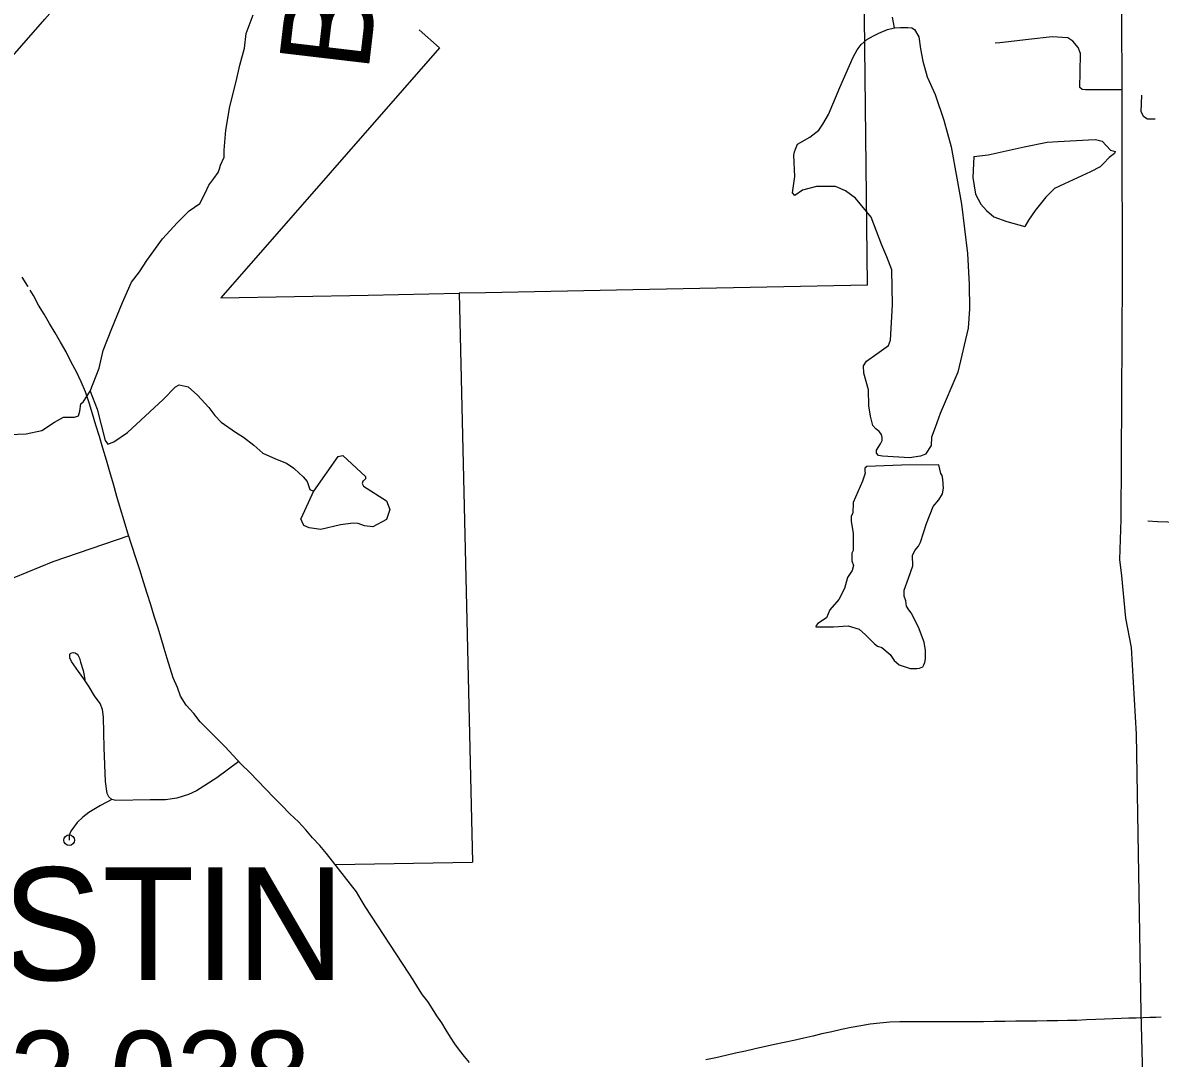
# Model space of a CAD drawing. Extents: x 1367863 to 1368197, y 380048 to 380261.
# Drawn here: x 1367991.45 to 1368012.13, y 380131.45 to 380150.28 of the extents above; entities that cross this region are included whole.
import ezdxf

# ---------------------------------------------------------------- set-up
doc = ezdxf.new("R2010")
doc.units = 0
for name, color, linetype in [('Level 10', 7, 'Continuous'), ('Level 33', 7, 'Continuous'), ('Level 35', 7, 'Continuous'), ('Level 40', 7, 'Continuous'), ('Level 6', 7, 'Continuous')]:
    doc.layers.add(name, color=color, linetype=linetype)

msp = doc.modelspace()

# ---------------------------------------------------------------- linework, layer by layer
at = {"layer": 'Level 10'}
msp.add_lwpolyline([(1368011.429, 380151.098), (1368011.439, 380145.66), (1368011.416, 380141.25), (1368011.392, 380140.52), (1368011.431, 380140.222), (1368011.504, 380139.453), (1368011.603, 380138.92), (1368011.693, 380137.345), (1368011.778, 380132.275), (1368011.845, 380129.756)], dxfattribs=at)
at = {"layer": 'Level 33'}
for points in [[(1368011.433, 380149.062), (1368010.774, 380149.061), (1368010.716, 380149.072), (1368010.669, 380149.107), (1368010.675, 380149.386), (1368010.681, 380149.724), (1368010.64, 380149.834), (1368010.547, 380149.951), (1368010.454, 380150.009), (1368010.169, 380150.026), (1368009.739, 380149.98), (1368009.216, 380149.916), (1368009.131, 380149.914)], [(1368012.041, 380148.531), (1368011.9, 380148.53), (1368011.836, 380148.571), (1368011.784, 380148.664), (1368011.796, 380148.966)], [(1367991.541, 380145.483), (1367991.537, 380145.49), (1367991.435, 380145.654)], [(1367997.518, 380134.473), (1367996.972, 380135.175), (1367996.846, 380135.316), (1367996.717, 380135.46), (1367996.591, 380135.604), (1367996.461, 380135.749), (1367996.305, 380135.896), (1367996.16, 380136.044), (1367996.014, 380136.193), (1367995.869, 380136.342), (1367995.721, 380136.494), (1367995.573, 380136.646), (1367995.417, 380136.8), (1367995.271, 380136.957), (1367995.124, 380137.112), (1367994.975, 380137.265), (1367994.825, 380137.418), (1367994.674, 380137.567), (1367994.559, 380137.72), (1367994.415, 380137.874), (1367994.317, 380138.032), (1367994.257, 380138.192), (1367994.178, 380138.368), (1367994.128, 380138.542), (1367994.074, 380138.72), (1367994.015, 380138.901), (1367993.961, 380139.092), (1367993.9, 380139.289), (1367993.837, 380139.49), (1367993.772, 380139.695), (1367993.706, 380139.903), (1367993.64, 380140.116), (1367993.573, 380140.332), (1367993.501, 380140.551), (1367993.428, 380140.773), (1367993.358, 380140.997), (1367993.292, 380141.225), (1367993.222, 380141.443), (1367993.157, 380141.665), (1367993.095, 380141.894), (1367993.03, 380142.114), (1367992.966, 380142.329), (1367992.904, 380142.544), (1367992.842, 380142.757), (1367992.777, 380142.967), (1367992.714, 380143.171), (1367992.651, 380143.369), (1367992.584, 380143.568), (1367992.508, 380143.755), (1367992.421, 380143.933), (1367992.325, 380144.111), (1367992.237, 380144.301), (1367992.134, 380144.476), (1367992.032, 380144.644), (1367991.932, 380144.813), (1367991.836, 380144.983), (1367991.732, 380145.146), (1367991.638, 380145.323), (1367991.578, 380145.421)], [(1368016.652, 380141.063), (1368016.403, 380141.048), (1368015.83, 380141.068), (1368015.058, 380141.093), (1368014.301, 380141.113), (1368013.479, 380141.148), (1368012.642, 380141.188), (1368012.084, 380141.207), (1368011.907, 380141.218)], [(1367993.372, 380140.951), (1367991.99, 380140.48), (1367991.286, 380140.188), (1367991.207, 380140.128), (1367991.129, 380140.017), (1367991.068, 380139.864), (1367991.05, 380139.641), (1367991.045, 380139.294)], [(1367995.375, 380136.846), (1367994.974, 380136.547), (1367994.605, 380136.312), (1367994.461, 380136.245), (1367994.25, 380136.177), (1367994.039, 380136.149), (1367993.765, 380136.149), (1367993.137, 380136.139), (1367993.065, 380136.158), (1367993.008, 380136.206), (1367992.979, 380136.264), (1367992.95, 380136.48), (1367992.926, 380137.094), (1367992.912, 380137.655), (1367992.893, 380137.794), (1367992.854, 380137.9), (1367992.749, 380138.039), (1367992.653, 380138.207), (1367992.557, 380138.35), (1367992.461, 380138.485), (1367992.332, 380138.667), (1367992.303, 380138.734), (1367992.303, 380138.797), (1367992.317, 380138.816), (1367992.361, 380138.83), (1367992.399, 380138.825), (1367992.432, 380138.801), (1367992.456, 380138.773), (1367992.476, 380138.729), (1367992.495, 380138.653), (1367992.543, 380138.504), (1367992.562, 380138.408), (1367992.576, 380138.331)], [(1367993.065, 380136.158), (1367992.859, 380136.045), (1367992.648, 380135.92), (1367992.538, 380135.834), (1367992.437, 380135.738), (1367992.317, 380135.58), (1367992.289, 380135.508), (1367992.289, 380135.416)], [(1367999.571, 380131.374), (1367999.479, 380131.481), (1367999.388, 380131.595), (1367999.303, 380131.712), (1367999.224, 380131.835), (1367999.147, 380131.962), (1367999.067, 380132.091), (1367998.975, 380132.218), (1367998.899, 380132.349), (1367998.815, 380132.48), (1367998.718, 380132.605), (1367998.633, 380132.734), (1367998.545, 380132.874), (1367998.468, 380132.998), (1367997.676, 380134.211), (1367997.599, 380134.331), (1367997.518, 380134.473)], [(1368012.151, 380132.196), (1368012.051, 380132.192), (1368011.942, 380132.191), (1368011.823, 380132.186), (1368011.696, 380132.18), (1368011.562, 380132.175), (1368011.421, 380132.169), (1368011.273, 380132.164), (1368011.119, 380132.157), (1368010.96, 380132.151), (1368010.794, 380132.145), (1368010.619, 380132.137), (1368010.445, 380132.136), (1368010.265, 380132.131), (1368010.079, 380132.128), (1368009.89, 380132.126), (1368009.699, 380132.124), (1368009.506, 380132.123), (1368009.312, 380132.12), (1368009.115, 380132.115), (1368008.919, 380132.112), (1368008.722, 380132.11), (1368008.527, 380132.111), (1368008.335, 380132.111), (1368008.146, 380132.114), (1368007.955, 380132.112), (1368007.765, 380132.112), (1368007.577, 380132.111), (1368007.395, 380132.109), (1368007.214, 380132.103), (1368007.035, 380132.089), (1368006.86, 380132.069), (1368006.686, 380132.041), (1368006.51, 380132.007), (1368006.334, 380131.97), (1368006.158, 380131.932), (1368005.981, 380131.892), (1368005.815, 380131.853), (1368005.65, 380131.813), (1368005.469, 380131.771), (1368005.294, 380131.734), (1368005.119, 380131.696), (1368004.765, 380131.618), (1368004.588, 380131.58), (1368004.409, 380131.539), (1368004.23, 380131.497), (1368004.05, 380131.455), (1368003.871, 380131.421)]]:
    msp.add_lwpolyline(points, dxfattribs=at)
msp.add_circle((1367992.289, 380135.416), 0.097, dxfattribs=at)
at = {"layer": 'Level 35'}
for points in [[(1367995.002, 380147.561), (1367995.023, 380147.628), (1367995.04, 380147.691), (1367995.107, 380147.842), (1367995.111, 380147.967), (1367995.136, 380148.332), (1367995.212, 380148.759), (1367995.329, 380149.216), (1367995.396, 380149.513), (1367995.48, 380149.819), (1367995.509, 380150.087), (1367995.635, 380150.426)], [(1368007.301, 380150.194), (1368007.264, 380150.387)], [(1368007.662, 380150.159), (1368007.743, 380150.026), (1368007.772, 380149.811), (1368007.813, 380149.584), (1368007.895, 380149.299), (1368008.04, 380148.979), (1368008.197, 380148.513), (1368008.331, 380148.025), (1368008.435, 380147.455), (1368008.517, 380146.983), (1368008.627, 380146.084), (1368008.656, 380145.52), (1368008.662, 380145.078), (1368008.639, 380144.728), (1368008.453, 380143.928), (1368008.133, 380143.178), (1368008.04, 380142.922), (1368007.976, 380142.747), (1368007.97, 380142.596), (1368007.866, 380142.439), (1368007.772, 380142.398), (1368007.575, 380142.369), (1368007.08, 380142.398), (1368007.011, 380142.41), (1368006.976, 380142.456), (1368006.976, 380142.509), (1368007.046, 380142.625), (1368007.075, 380142.683), (1368007.075, 380142.742), (1368007.063, 380142.794), (1368007.022, 380142.852), (1368006.964, 380142.899), (1368006.906, 380142.957), (1368006.865, 380143.126), (1368006.836, 380143.317), (1368006.825, 380143.608), (1368006.743, 380143.911), (1368006.737, 380144.045), (1368006.79, 380144.126), (1368006.982, 380144.26), (1368007.191, 380144.411), (1368007.226, 380144.51), (1368007.267, 380145.156), (1368007.249, 380145.79), (1368007.162, 380146.028), (1368007.069, 380146.238), (1368006.877, 380146.746), (1368006.592, 380147.095), (1368006.412, 380147.229), (1368006.226, 380147.304), (1368005.882, 380147.304), (1368005.627, 380147.24), (1368005.487, 380147.141), (1368005.446, 380147.188), (1368005.487, 380147.49), (1368005.47, 380147.874), (1368005.481, 380147.938), (1368005.499, 380147.985), (1368005.539, 380148.077)], [(1368005.539, 380148.077), (1368005.76, 380148.205), (1368005.923, 380148.333), (1368005.999, 380148.437), (1368006.098, 380148.618), (1368006.307, 380149.106), (1368006.551, 380149.659), (1368006.621, 380149.793), (1368006.697, 380149.886), (1368006.796, 380149.979), (1368006.918, 380150.049), (1368007.016, 380150.095), (1368007.174, 380150.159), (1368007.301, 380150.194), (1368007.412, 380150.2), (1368007.546, 380150.2), (1368007.615, 380150.194), (1368007.662, 380150.159)], [(1368008.744, 380147.85), (1368009.005, 380147.879), (1368009.657, 380148.025), (1368010.075, 380148.112), (1368010.279, 380148.124), (1368010.831, 380148.153), (1368010.954, 380148.159), (1368011.076, 380148.129), (1368011.227, 380147.967), (1368011.314, 380147.943), (1368011.302, 380147.908), (1368011.204, 380147.833), (1368011.099, 380147.722), (1368011.041, 380147.664), (1368010.866, 380147.571), (1368010.395, 380147.356), (1368010.209, 380147.268), (1368010.052, 380147.111), (1368009.86, 380146.867), (1368009.738, 380146.692), (1368009.668, 380146.576)], [(1368008.744, 380147.85), (1368008.726, 380147.471), (1368008.773, 380147.163), (1368008.872, 380146.983), (1368008.976, 380146.866), (1368009.11, 380146.756), (1368009.343, 380146.669), (1368009.668, 380146.576)], [(1367991.053, 380142.789), (1367991.509, 380142.806), (1367991.79, 380142.869), (1367992.025, 380143.019), (1367992.188, 380143.107), (1367992.385, 380143.112), (1367992.46, 380143.133), (1367992.481, 380143.221), (1367992.502, 380143.35), (1367992.548, 380143.397), (1367992.67, 380143.581), (1367992.833, 380144), (1367992.908, 380144.322), (1367993.063, 380144.72), (1367993.26, 380145.198), (1367993.423, 380145.567), (1367993.566, 380145.751), (1367993.704, 380145.96), (1367993.985, 380146.354), (1367994.257, 380146.652), (1367994.474, 380146.865), (1367994.667, 380146.999), (1367994.763, 380147.184), (1367994.83, 380147.33), (1367994.918, 380147.452), (1367995.002, 380147.561)], [(1367992.67, 380143.581), (1367992.796, 380143.257), (1367992.943, 380142.683), (1367992.995, 380142.62), (1367993.099, 380142.662), (1367993.35, 380142.829), (1367993.997, 380143.434), (1367994.226, 380143.664), (1367994.289, 380143.695), (1367994.456, 380143.664), (1367994.623, 380143.507), (1367994.832, 380143.288), (1367994.936, 380143.142), (1367995.051, 380143.017), (1367995.312, 380142.839), (1367995.458, 380142.745), (1367995.646, 380142.599), (1367995.813, 380142.453), (1367996.042, 380142.349), (1367996.241, 380142.275), (1367996.376, 380142.181), (1367996.387, 380142.171), (1367996.543, 380142.025), (1367996.617, 380141.941), (1367996.669, 380141.795), (1367996.732, 380141.764)], [(1367997.178, 380142.395), (1367997.267, 380142.414), (1367997.681, 380142.032), (1367997.681, 380141.987), (1367997.637, 380141.943), (1367997.63, 380141.943), (1367997.617, 380141.904), (1367997.643, 380141.853), (1367998.063, 380141.586), (1367998.121, 380141.433), (1367998.063, 380141.248), (1367997.815, 380141.114), (1367997.662, 380141.133), (1367997.547, 380141.178), (1367997.452, 380141.184), (1367997.222, 380141.152), (1367996.865, 380141.069), (1367996.655, 380141.095), (1367996.56, 380141.139), (1367996.528, 380141.203), (1367996.502, 380141.261)], [(1367997.178, 380142.395), (1367996.732, 380141.764), (1367996.502, 380141.261)], [(1368006.799, 380142.21), (1368006.761, 380142.181), (1368006.761, 380142.124), (1368006.767, 380142.089), (1368006.718, 380141.948), (1368006.551, 380141.555), (1368006.542, 380141.362), (1368006.511, 380141.307), (1368006.511, 380141.221), (1368006.548, 380140.993), (1368006.548, 380140.685), (1368006.525, 380140.633), (1368006.525, 380140.499), (1368006.557, 380140.412), (1368006.531, 380140.323), (1368006.447, 380140.193), (1368006.389, 380139.994), (1368006.291, 380139.795), (1368006.127, 380139.608), (1368006.061, 380139.458), (1368005.905, 380139.357), (1368005.873, 380139.322), (1368005.868, 380139.294), (1368005.937, 380139.294), (1368006.193, 380139.294), (1368006.459, 380139.314), (1368006.658, 380139.253), (1368006.776, 380139.152), (1368006.937, 380138.984), (1368006.989, 380138.946), (1368007.073, 380138.92), (1368007.22, 380138.793), (1368007.297, 380138.684), (1368007.387, 380138.603), (1368007.511, 380138.56), (1368007.586, 380138.54), (1368007.707, 380138.537), (1368007.753, 380138.543), (1368007.813, 380138.569), (1368007.836, 380138.603), (1368007.851, 380138.646), (1368007.862, 380138.716), (1368007.865, 380138.863), (1368007.842, 380139.016), (1368007.738, 380139.289), (1368007.603, 380139.548), (1368007.56, 380139.608), (1368007.516, 380139.672), (1368007.508, 380139.767), (1368007.479, 380139.856), (1368007.476, 380139.966), (1368007.554, 380140.183), (1368007.632, 380140.408), (1368007.629, 380140.593), (1368007.672, 380140.682), (1368007.738, 380140.763), (1368007.776, 380140.835), (1368007.885, 380141.178), (1368008.001, 380141.487), (1368008.107, 380141.605), (1368008.171, 380141.714), (1368008.191, 380141.818), (1368008.182, 380141.983), (1368008.168, 380142.049), (1368008.145, 380142.086), (1368008.107, 380142.242)], [(1368008.107, 380142.242), (1368007.43, 380142.236), (1368006.799, 380142.21)]]:
    msp.add_lwpolyline(points, dxfattribs=at)
at = {"layer": 'Level 40'}
for points in [[(1367989.355, 380147.507), (1367991.846, 380150.349), (1367993.31, 380152.01), (1367995.255, 380154.24), (1367997.659, 380156.983), (1367999.101, 380158.645), (1368000.784, 380160.612), (1368001.166, 380161.093), (1368001.865, 380162.022), (1368002.903, 380163.465), (1368003.701, 380164.536), (1368005.384, 380166.853), (1368006.389, 380168.208), (1368007.897, 380170.285), (1368009.536, 380172.515), (1368010.803, 380174.253), (1368012.366, 380176.384), (1368013.156, 380177.46)], [(1367989.355, 380147.507), (1367991.846, 380150.349), (1367993.31, 380152.01), (1367995.255, 380154.24), (1367997.659, 380156.983), (1367999.101, 380158.645), (1368000.784, 380160.612), (1368001.166, 380161.093), (1368001.865, 380162.022), (1368002.903, 380163.465), (1368003.701, 380164.536), (1368005.384, 380166.853), (1368006.389, 380168.208), (1368007.897, 380170.285), (1368009.536, 380172.515), (1368010.803, 380174.253), (1368012.366, 380176.384)]]:
    msp.add_lwpolyline(points, dxfattribs=at)
at = {"layer": 'Level 6'}
for points in [[(1368006.812, 380145.508), (1368006.692, 380155.797)], [(1367998.656, 380150.158), (1367999.024, 380149.825), (1367995.045, 380145.279)], [(1368006.812, 380145.508), (1368002.541, 380145.425), (1367999.86, 380145.373), (1367999.383, 380145.363)], [(1367995.045, 380145.279), (1367997.728, 380145.331), (1367999.383, 380145.363)], [(1367999.383, 380145.363), (1367999.625, 380135.013)], [(1367999.383, 380145.363), (1367999.625, 380135.013)], [(1367997.128, 380134.973), (1367999.625, 380135.013)], [(1367997.128, 380134.973), (1367999.625, 380135.013)]]:
    msp.add_lwpolyline(points, dxfattribs=at)

# ---------------------------------------------------------------- texts
at = {"layer": 'Level 35'}
msp.add_text('Br.', height=1.6394, rotation=83.289, dxfattribs=at).set_placement((1367997.728, 380149.365))
at = {"layer": 'Level 6'}
for s, height, p in [('AUSTIN', 2.0492, (1367987.257, 380132.87)), ('Pop. 2,038', 1.6394, (1367986.08, 380130.307))]:
    msp.add_text(s, height=height, dxfattribs=at).set_placement(p)

doc.saveas('drawing.dxf')
